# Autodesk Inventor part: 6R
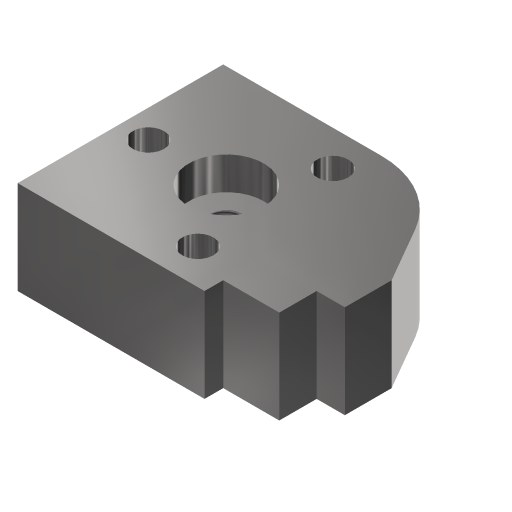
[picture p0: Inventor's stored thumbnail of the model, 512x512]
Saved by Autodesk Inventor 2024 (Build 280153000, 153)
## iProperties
Company: ATC
Created: 2023-03
Part Number: 6R
Material: 18G2A-Rez.
Document SubType Name: Modeling
Designer: Andrzej Jaskulski
Manufacturer: Standard
Standards Organization: Custom
Density: 1 g/cm^3
Appearance: Stal — polerowana
Checked By: A.J.
Engr Approved By: Andrzej Jaskulski
Mfg Approved By: Andrzej Jaskulski
Authority: A.J.
Moduł_X: 3,000 mm
Title: A.J.: Kurs R2024-MEP
Author: Andrzej Jaskulski
Revision Number: 1/24
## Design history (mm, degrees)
sketch "Szkic1"
  geometry: L1 (0, 0)-(60, 0); L2 (60, 0)-(60, 6); L3 (60, 6)-(78, 6); L4 (78, 6)-(78, 18); L5 (78, 18)-(87.053, 18); L6 (87.053, 18)-(87.053, 33); L7 (87.053, 33)-(68, 66); L8 (68, 66)-(0, 66); L9 (0, 66)-(0, 0)
  constraints: 18 end point, 6 parallel, 1 horizontal, 1 perpendicular, 1 other
  dimensions: "d0" = 60 distance of L1.start L1.end (= 20 x Moduł_X); "d1" = 18 distance of L2.end L3.end (= 6 x Moduł_X); "d2" = 9.05256 distance of L4.end L5.end (derived); "d3" = 66 distance of L8.end L1.start (= 22 x Moduł_X); "d4" = 150 deg angle of L7 L6; "d5" = 6 distance of L1.end L2.end (= 2 x Moduł_X); "d6" = 12 distance of L3.end L4.end (= 4 x Moduł_X); "d7" = 15 distance of L5.end L6.end (= 5 x Moduł_X); "d19" = 68 distance of L7.end L8.end
extrude "BAZA" new body sketch "Szkic1" distance "d8" = 30 (= 10 x Moduł_X); taper "d9" = 0 deg
hole "Otwór M12" diameter "d12" = 10.106; stored, may be unused: countersink angle "d16" = 90 deg, drill point angle "d18" = 118 deg; dims "d10" = 34 (= 0.5 x d19), "d11" = 33 (= 0.5 x d3), "d13" = 24 (= 8 x Moduł_X), "d14" = 24, "d15" = 10.5, "d17" = 8
node "Oś otw. M12"
node "Pł. Symetrii"
sketch "Szkic2"
  geometry: L1 (104.463, 33)-(-17.411, 33) reference; 2 further points
  constraints: 1 point on line
  dimensions: "d21" = 25 distance of point (34, 33) point (9, 33) (computed from d19)
hole "Otwór Fi10" sketch "Szkic2" diameter "d22" = 10; stored, may be unused: countersink angle "d26" = 90 deg, drill point angle "d28" = 118 deg; dims "d23" = 6, "d24" = 3.6, "d25" = 5.3, "d27" = 8
node "Oś Oryginału"
pattern_circular "Szyk kołowy 1" dims angle "d31" = 360 deg
fillet "Zaokrąglenie1" dims "d32" = 30
node "Bryła1"
node "Korpusy bryłowe"
node "Korpusy powierzchniowe"
other parameters: "Moduł_X" = 3 [user parameter; used in 8 equation terms], "d20" = 0
